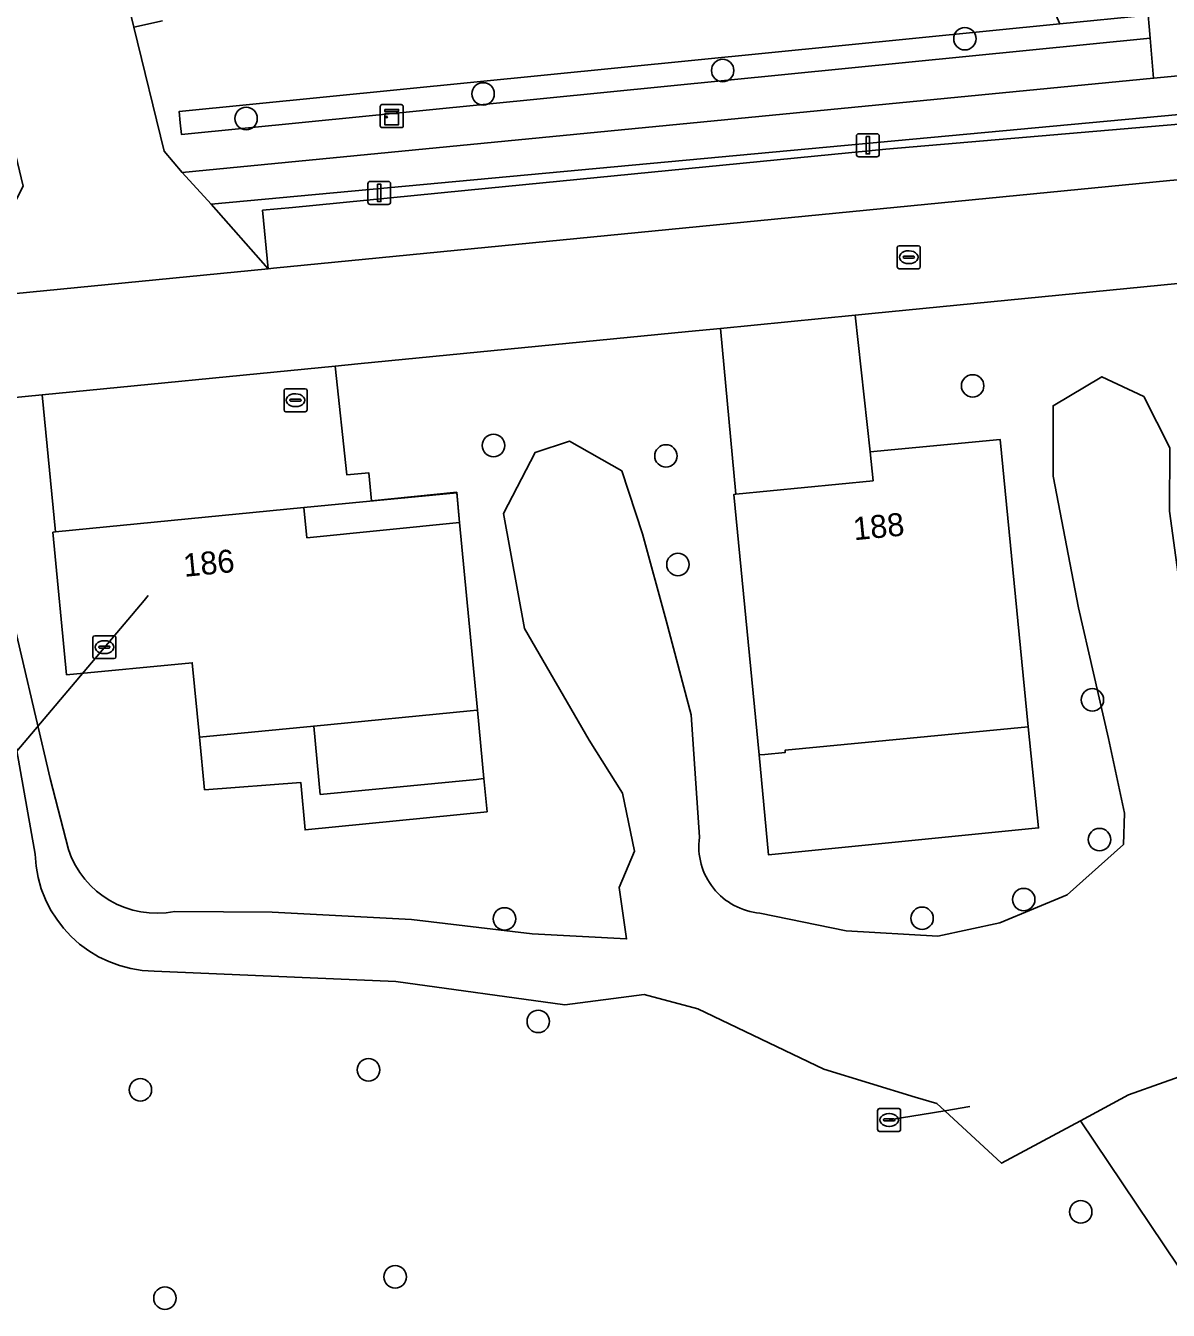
# Model space of a CAD drawing. Extents: x 156661 to 157576, y 383570 to 384425.
# Drawn here: x 156959.7 to 157009.5, y 383880.2 to 383936.2 of the extents above; entities that cross this region are included whole.
import ezdxf

# ---------------------------------------------------------------- set-up
doc = ezdxf.new("R2010")
doc.units = 0
for name, color, linetype in [('IMGEO_Berm_groen', 7, 'Continuous'), ('IMGEO_Boom', 7, 'Continuous'), ('IMGEO_Brandkraan', 7, 'Continuous'), ('IMGEO_Duiker', 7, 'Continuous'), ('IMGEO_Erf', 7, 'Continuous'), ('IMGEO_Groenvoorziening', 7, 'Continuous'), ('IMGEO_Haag', 7, 'Continuous'), ('IMGEO_Kast', 7, 'Continuous'), ('IMGEO_Lichtmast', 7, 'Continuous'), ('IMGEO_Meer_plas_ven_vijver', 7, 'Continuous'), ('IMGEO_Pand', 7, 'Continuous'), ('IMGEO_Pand_nummerreeks', 7, 'Continuous'), ('IMGEO_Pand_overbouw', 7, 'Continuous'), ('IMGEO_Parkeervlak_open', 7, 'Continuous'), ('IMGEO_Rijbaan_lokaal_open', 7, 'Continuous'), ('IMGEO_Rioolput', 7, 'Continuous'), ('IMGEO_Voetpad_open', 7, 'Continuous')]:
    doc.layers.add(name, color=color, linetype=linetype)

msp = doc.modelspace()

# ---------------------------------------------------------------- linework, layer by layer
at = {"layer": 'IMGEO_Berm_groen'}
msp.add_lwpolyline([(157071.526, 383937.018), (157071.115, 383937.537), (157053.882, 383936.219), (157047.285, 383935.737), (157032.066, 383934.37), (156967.792, 383928.413), (156970.285, 383925.601), (156970.036, 383928.144), (156971.344, 383928.273), (156979.881, 383929.112), (156997.191, 383930.813), (157022.212, 383932.944), (157037.851, 383934.234), (157045.273, 383934.895), (157055.512, 383935.702), (157055.71, 383933.229), (157057.249, 383933.355), (157057.154, 383934.404), (157058.945, 383934.553), (157058.941, 383934.597), (157071.071, 383935.569)], dxfattribs=at)
at = {"layer": 'IMGEO_Boom'}
for centre in [(157000.632, 383935.62), (156990.079, 383934.237), (156979.643, 383933.214), (156969.318, 383932.144), (157000.969, 383920.497), (156980.097, 383917.899), (156987.609, 383917.445), (156988.131, 383912.717), (157006.183, 383906.821), (157006.493, 383900.734), (157003.192, 383898.123), (156980.577, 383897.281), (156998.764, 383897.307), (156982.046, 383892.817), (156974.65, 383890.706), (156964.713, 383889.834), (157005.677, 383884.524), (156975.812, 383881.692), (156965.784, 383880.761)]:
    msp.add_circle(centre, 0.489, dxfattribs=at)
at = {"layer": 'IMGEO_Brandkraan'}
for p, q in [((156970.971, 383919.448), (156970.971, 383920.3)), ((156971.046, 383920.374), (156971.898, 383920.374)), ((156971.972, 383920.3), (156971.972, 383919.448)), ((156971.23, 383919.868), (156971.23, 383919.88)), ((156971.668, 383919.831), (156971.27, 383919.831)), ((156971.273, 383919.917), (156971.671, 383919.917)), ((156971.459, 383920.154), (156971.484, 383920.154)), ((156971.714, 383919.88), (156971.714, 383919.868)), ((156971.898, 383919.374), (156971.046, 383919.374)), ((156971.482, 383919.594), (156971.457, 383919.594))]:
    msp.add_line(p, q, dxfattribs=at)
for points in [[(156970.971, 383919.448), (156970.971, 383920.3)], [(156971.046, 383920.374), (156971.898, 383920.374)], [(156971.972, 383920.3), (156971.972, 383919.448)], [(156971.898, 383919.374), (156971.046, 383919.374)]]:
    msp.add_lwpolyline(points, dxfattribs=at)
for centre, radius, start, end in [((156971.048, 383920.298), 0.0765, 91.552, 178.448), ((156971.048, 383920.298), 0.0765, 91.552, 178.448), ((156971.896, 383920.298), 0.0765, 1.552, 88.448), ((156971.896, 383920.298), 0.0765, 1.552, 88.448), ((156971.27, 383919.877), 0.0403, 85.8775, 175.7526), ((156971.267, 383919.867), 0.0366, 178.938, 274.7102), ((156971.671, 383919.874), 0.043, 264.8664, 352.4533), ((156971.675, 383919.879), 0.0386, 1.7309, 96.639), ((156971.048, 383919.45), 0.0765, 181.552, 268.448), ((156971.048, 383919.45), 0.0765, 181.552, 268.448), ((156971.896, 383919.45), 0.0765, 271.552, 358.448), ((156971.896, 383919.45), 0.0765, 271.552, 358.448)]:
    msp.add_arc(centre, radius, start, end, dxfattribs=at)
for centre, major_axis, ratio, start_param, end_param in [((156971.458, 383919.874), (-0.387, 0.002), 0.722429, 4.712389, 7.853982), ((156971.483, 383919.874), (-0.39, 0.002), 0.717154, 1.570796, 4.712389)]:
    msp.add_ellipse(centre, major_axis=major_axis, ratio=ratio, start_param=start_param, end_param=end_param, dxfattribs=at)
at = {"layer": 'IMGEO_Duiker'}
for points in [[(156965.051, 383911.364), (156964.873, 383911.153), (156956.467, 383901.225), (156955.878, 383900.53)], [(157000.842, 383889.109), (156999.755, 383888.928), (156997.332, 383888.523)]]:
    msp.add_lwpolyline(points, dxfattribs=at)
at = {"layer": 'IMGEO_Erf'}
for points in [[(156995.853, 383923.576), (156989.991, 383923.001), (156990.652, 383915.775), (156996.635, 383916.363), (156996.502, 383917.63)], [(156973.202, 383921.355), (156960.429, 383920.102), (156961.014, 383914.134), (156971.834, 383915.203), (156971.965, 383913.88), (156978.62, 383914.545), (156978.494, 383915.861), (156974.785, 383915.495), (156974.663, 383916.711), (156973.714, 383916.616)], [(156979.403, 383906.377), (156979.379, 383906.375), (156979.075, 383906.345), (156972.265, 383905.678), (156967.284, 383905.192), (156967.509, 383902.905), (156971.708, 383903.217), (156971.891, 383901.154), (156979.814, 383901.951), (156979.681, 383903.392)], [(157003.391, 383905.643), (156992.795, 383904.629), (156992.805, 383904.534), (156991.921, 383904.448), (156991.674, 383904.424), (156992.08, 383900.065), (157003.838, 383901.242)]]:
    msp.add_lwpolyline(points, close=True, dxfattribs=at)
at = {"layer": 'IMGEO_Groenvoorziening'}
for points in [[(156953.099, 383937.896), (156882.007, 383929.988), (156863.465, 384006.689), (156971.911, 384032.865), (156984.848, 383993.384), (157001.305, 383943.16), (156963.71, 383939.037), (156964.423, 383936.119), (156965.671, 383936.392)], [(157002.87, 383940.558), (157004.772, 383936.263), (157008.609, 383936.644), (157008.658, 383936.146), (157008.707, 383935.648), (157008.85, 383933.899), (157012.523, 383934.255), (157027.632, 383935.51), (157049.754, 383937.359)], [(156965.671, 383936.392), (156964.423, 383936.119), (156965.744, 383930.718), (156966.535, 383929.792), (157008.85, 383933.899), (157008.707, 383935.648), (156966.501, 383931.453), (156966.452, 383931.95), (156966.402, 383932.448), (157004.772, 383936.263)], [(157009.913, 383924.955), (156996.578, 383923.647), (156995.853, 383923.576), (156996.502, 383917.63), (157002.161, 383918.165), (157003.391, 383905.643), (157003.838, 383901.242), (156992.08, 383900.065), (156991.674, 383904.424), (156990.563, 383915.766), (156990.652, 383915.775), (156989.991, 383923.001), (156988.593, 383922.864), (156974.187, 383921.452), (156973.202, 383921.355), (156973.714, 383916.616), (156974.663, 383916.711), (156974.785, 383915.495), (156978.494, 383915.861), (156978.62, 383914.545), (156979.403, 383906.377), (156979.681, 383903.392), (156979.814, 383901.951), (156971.891, 383901.154), (156971.708, 383903.217), (156967.509, 383902.905), (156967.284, 383905.192), (156966.971, 383908.439), (156961.498, 383907.912), (156960.9, 383914.123), (156961.014, 383914.134), (156960.429, 383920.102), (156912.352, 383915.387)], [(156991.704, 383897.533), (156995.46, 383896.76), (156999.448, 383896.532), (157002.147, 383897.105), (157005.086, 383898.333), (157007.547, 383900.528), (157007.587, 383901.882), (157006.883, 383905.138), (157005.579, 383910.832), (157004.482, 383916.564), (157004.469, 383919.634), (157006.599, 383920.898), (157008.421, 383920.042), (157009.558, 383917.804), (157009.548, 383915.038), (157010.137, 383910.688), (157011.147, 383905.321), (157012.775, 383900.932)], [(156966.214, 383897.609), (156970.461, 383897.569), (156976.53, 383897.255), (156981.775, 383896.629), (156985.893, 383896.412), (156985.576, 383898.642), (156986.234, 383900.228), (156985.71, 383902.762), (156984.257, 383905.07), (156981.444, 383909.929), (156980.534, 383914.932), (156981.914, 383917.602), (156983.408, 383918.095), (156985.69, 383916.795), (156986.591, 383914.049), (156987.619, 383910.28), (156988.702, 383906.17), (156989.065, 383900.834)], [(156960.124, 383900.103), (156957.522, 383914.747), (156958.361, 383914.954), (156958.91, 383911.412), (156960.786, 383903.39), (156961.584, 383900.301)], [(157016.422, 383876.906), (157011.144, 383880.337), (157005.669, 383888.491), (157002.231, 383886.636), (156999.755, 383888.928), (156999.413, 383889.244), (156998.463, 383889.523), (156994.479, 383890.731), (156988.991, 383893.36), (156986.656, 383893.993), (156983.208, 383893.538), (156975.842, 383894.559), (156965.319, 383894.998)]]:
    msp.add_lwpolyline(points, dxfattribs=at)
for points in [[(157008.707, 383935.648), (157008.658, 383936.146), (157008.609, 383936.644), (157004.772, 383936.263), (156966.402, 383932.448), (156966.452, 383931.95), (156966.501, 383931.453)], [(157058.511, 383896.433), (157058.506, 383896.82), (157058.418, 383896.745), (157055.904, 383896.289), (157051.303, 383896.382), (157048.983, 383894.367), (157045.629, 383892.859), (157041.142, 383892.89), (157033.089, 383893.802), (157029.876, 383893.975), (157025.097, 383892.911), (157015.681, 383891.686), (157010.865, 383890.715), (157007.751, 383889.615), (157005.669, 383888.491), (157011.144, 383880.337), (157016.422, 383876.906), (157031.991, 383867.671), (157048.615, 383859.226), (157052.837, 383866.747), (157055.608, 383875.059), (157057.323, 383883.635)]]:
    msp.add_lwpolyline(points, close=True, dxfattribs=at)
for centre, radius, start, end in [((156991.957, 383900.441), 2.919, 172.2587, 265.0228), ((156965.417, 383901.565), 4.036, 198.2547, 281.3957), ((156965.407, 383900.283), 5.286, 181.9547, 269.0466)]:
    msp.add_arc(centre, radius, start, end, dxfattribs=at)
at = {"layer": 'IMGEO_Haag'}
msp.add_lwpolyline([(157008.707, 383935.648), (157008.658, 383936.146), (157008.609, 383936.644), (157004.772, 383936.263), (156966.402, 383932.448), (156966.452, 383931.95), (156966.501, 383931.453)], close=True, dxfattribs=at)
at = {"layer": 'IMGEO_Kast'}
for p, q in [((156975.163, 383931.822), (156975.163, 383932.663)), ((156975.163, 383932.663), (156975.163, 383931.822)), ((156975.238, 383932.747), (156976.079, 383932.747)), ((156976.079, 383932.747), (156975.238, 383932.747)), ((156976.163, 383932.672), (156976.163, 383931.831)), ((156976.163, 383931.831), (156976.163, 383932.672)), ((156976.088, 383931.747), (156975.247, 383931.747)), ((156975.247, 383931.747), (156976.088, 383931.747))]:
    msp.add_line(p, q, dxfattribs=at)
for points in [[(156975.358, 383932.537), (156975.958, 383932.537), (156975.958, 383932.452), (156975.358, 383932.452), (156975.358, 383932.537)], [(156975.358, 383932.362), (156975.958, 383932.362), (156975.958, 383931.873), (156975.358, 383931.873), (156975.358, 383932.362)]]:
    msp.add_lwpolyline(points, dxfattribs=at)
msp.add_circle((156975.442, 383932.211), 0.0377, dxfattribs=at)
for centre, start, end in [((156975.241, 383932.669), 92.4484, 184.2845), ((156975.241, 383932.669), 92.4484, 184.2845), ((156976.085, 383932.669), 2.4484, 94.2845), ((156976.085, 383932.669), 2.4484, 94.2845), ((156975.241, 383931.825), 182.4484, 274.2845), ((156975.241, 383931.825), 182.4484, 274.2845), ((156976.085, 383931.825), 272.4484, 4.2845), ((156976.085, 383931.825), 272.4484, 4.2845)]:
    msp.add_arc(centre, 0.0779, start, end, dxfattribs=at)
at = {"layer": 'IMGEO_Lichtmast'}
for p, q in [((156995.908, 383930.579), (156995.908, 383931.379)), ((156995.908, 383931.379), (156995.908, 383930.579)), ((156996.008, 383931.479), (156996.798, 383931.479)), ((156996.798, 383931.479), (156996.008, 383931.479)), ((156996.898, 383931.379), (156996.898, 383930.579)), ((156996.898, 383930.579), (156996.898, 383931.379)), ((156996.798, 383930.479), (156996.008, 383930.479)), ((156996.008, 383930.479), (156996.798, 383930.479)), ((156974.624, 383928.503), (156974.624, 383929.303)), ((156974.624, 383929.303), (156974.624, 383928.503)), ((156974.724, 383929.403), (156975.514, 383929.403)), ((156975.514, 383929.403), (156974.724, 383929.403)), ((156975.614, 383929.303), (156975.614, 383928.503)), ((156975.614, 383928.503), (156975.614, 383929.303)), ((156975.514, 383928.403), (156974.724, 383928.403)), ((156974.724, 383928.403), (156975.514, 383928.403))]:
    msp.add_line(p, q, dxfattribs=at)
for points in [[(156996.328, 383931.354), (156996.478, 383931.354), (156996.478, 383930.604), (156996.328, 383930.604), (156996.328, 383931.354)], [(156975.044, 383929.278), (156975.194, 383929.278), (156975.194, 383928.528), (156975.044, 383928.528), (156975.044, 383929.278)]]:
    msp.add_lwpolyline(points, dxfattribs=at)
for centre, start, end in [((156996.008, 383931.379), 90, 180), ((156996.008, 383931.379), 90, 180), ((156996.798, 383931.379), 0, 90), ((156996.798, 383931.379), 360, 90), ((156996.008, 383930.579), 180, 270), ((156996.008, 383930.579), 180, 270), ((156996.798, 383930.579), 270, 0), ((156996.798, 383930.579), 270, 0), ((156974.724, 383929.303), 90, 180), ((156974.724, 383929.303), 90, 180), ((156975.514, 383929.303), 0, 90), ((156975.514, 383929.303), 360, 90), ((156974.724, 383928.503), 180, 270), ((156974.724, 383928.503), 180, 270), ((156975.514, 383928.503), 270, 0), ((156975.514, 383928.503), 270, 0)]:
    msp.add_arc(centre, 0.1, start, end, dxfattribs=at)
at = {"layer": 'IMGEO_Meer_plas_ven_vijver'}
for points in [[(157012.775, 383900.932), (157011.147, 383905.321), (157010.137, 383910.688), (157009.548, 383915.038), (157009.558, 383917.804), (157008.421, 383920.042), (157006.599, 383920.898), (157004.469, 383919.634), (157004.482, 383916.564), (157005.579, 383910.832), (157006.883, 383905.138), (157007.587, 383901.882), (157007.547, 383900.528), (157005.086, 383898.333), (157002.147, 383897.105), (156999.448, 383896.532), (156995.46, 383896.76), (156991.704, 383897.533)], [(156989.065, 383900.834), (156988.702, 383906.17), (156987.619, 383910.28), (156986.591, 383914.049), (156985.69, 383916.795), (156983.408, 383918.095), (156981.914, 383917.602), (156980.534, 383914.932), (156981.444, 383909.929), (156984.257, 383905.07), (156985.71, 383902.762), (156986.234, 383900.228), (156985.576, 383898.642), (156985.893, 383896.412), (156981.775, 383896.629), (156976.53, 383897.255), (156970.461, 383897.569), (156966.214, 383897.609)], [(156961.584, 383900.301), (156960.786, 383903.39), (156958.91, 383911.412), (156958.361, 383914.954), (156957.522, 383914.747), (156960.124, 383900.103)], [(156965.319, 383894.998), (156975.842, 383894.559), (156983.208, 383893.538), (156986.656, 383893.993), (156988.991, 383893.36), (156994.479, 383890.731), (156998.463, 383889.523), (156999.413, 383889.244), (156999.755, 383888.928), (157002.231, 383886.636), (157005.669, 383888.491), (157007.751, 383889.615), (157010.865, 383890.715), (157015.681, 383891.686), (157025.097, 383892.911), (157029.876, 383893.975), (157033.089, 383893.802), (157041.142, 383892.89), (157045.629, 383892.859), (157048.983, 383894.367), (157051.303, 383896.382), (157055.904, 383896.289), (157058.418, 383896.745), (157058.506, 383896.82)]]:
    msp.add_lwpolyline(points, dxfattribs=at)
for centre, radius, start, end in [((156991.957, 383900.441), 2.919, 172.2587, 265.0228), ((156965.417, 383901.565), 4.036, 198.2547, 281.3957), ((156965.407, 383900.283), 5.286, 181.9547, 269.0466)]:
    msp.add_arc(centre, radius, start, end, dxfattribs=at)
at = {"layer": 'IMGEO_Pand'}
for points in [[(157002.161, 383918.165), (156996.502, 383917.63), (156996.635, 383916.363), (156990.652, 383915.775), (156990.563, 383915.766), (156991.674, 383904.424), (156991.921, 383904.448), (156992.805, 383904.534), (156992.795, 383904.629), (157003.391, 383905.643)], [(156978.62, 383914.545), (156971.965, 383913.88), (156971.834, 383915.203), (156961.014, 383914.134), (156960.9, 383914.123), (156961.498, 383907.912), (156966.971, 383908.439), (156967.284, 383905.192), (156972.265, 383905.678), (156979.075, 383906.345), (156979.379, 383906.375), (156979.403, 383906.377)]]:
    msp.add_lwpolyline(points, close=True, dxfattribs=at)
at = {"layer": 'IMGEO_Pand_overbouw'}
for points in [[(156978.495, 383915.842), (156971.834, 383915.203), (156971.965, 383913.88), (156978.62, 383914.545)], [(156979.403, 383906.377), (156979.379, 383906.375), (156979.075, 383906.345), (156972.265, 383905.678), (156972.55, 383902.7), (156979.352, 383903.36), (156979.656, 383903.39), (156979.681, 383903.392)]]:
    msp.add_lwpolyline(points, close=True, dxfattribs=at)
at = {"layer": 'IMGEO_Parkeervlak_open'}
msp.add_lwpolyline([(157055.71, 383933.229), (157055.512, 383935.702), (157045.273, 383934.895), (157037.851, 383934.234), (157022.212, 383932.944), (156997.191, 383930.813), (156979.881, 383929.112), (156971.344, 383928.273), (156970.036, 383928.144), (156970.285, 383925.601), (156970.506, 383925.623), (157009.562, 383929.446)], close=True, dxfattribs=at)
at = {"layer": 'IMGEO_Rijbaan_lokaal_open'}
msp.add_lwpolyline([(156963.71, 383939.037), (156963.662, 383939.235), (156962.748, 383943.053), (156961.579, 383942.807), (156961.704, 383942.271), (156961.383, 383942.196), (156961.258, 383942.72), (156959.573, 383949.776), (156954.882, 383948.869), (156956.564, 383941.597), (156956.615, 383941.611), (156956.745, 383941.083), (156957.783, 383936.781), (156959.604, 383929.198), (156958.753, 383927.533), (156957.067, 383924.307), (156970.285, 383925.601), (156967.792, 383928.413), (156966.535, 383929.792), (156965.744, 383930.718), (156964.423, 383936.119)], close=True, dxfattribs=at)
for points in [[(157055.71, 383933.229), (157009.562, 383929.446), (156970.506, 383925.623), (156970.285, 383925.601), (156957.067, 383924.307)], [(156912.352, 383915.387), (156960.429, 383920.102), (156973.202, 383921.355), (156974.187, 383921.452), (156988.593, 383922.864), (156989.991, 383923.001), (156995.853, 383923.576), (156996.578, 383923.647), (157009.913, 383924.955), (157018.161, 383925.629), (157025.823, 383926.256), (157051.661, 383928.368)]]:
    msp.add_lwpolyline(points, dxfattribs=at)
at = {"layer": 'IMGEO_Rioolput'}
for p, q in [((156997.687, 383925.677), (156997.687, 383926.529)), ((156997.762, 383926.603), (156998.614, 383926.603)), ((156998.688, 383926.529), (156998.688, 383925.677)), ((156997.946, 383926.097), (156997.946, 383926.109)), ((156998.384, 383926.06), (156997.986, 383926.06)), ((156997.989, 383926.146), (156998.387, 383926.146)), ((156998.175, 383926.383), (156998.2, 383926.383)), ((156998.43, 383926.109), (156998.43, 383926.097)), ((156998.614, 383925.603), (156997.762, 383925.603)), ((156998.198, 383925.823), (156998.173, 383925.823)), ((156962.648, 383908.691), (156962.648, 383909.543)), ((156962.723, 383909.617), (156963.575, 383909.617)), ((156962.907, 383909.111), (156962.907, 383909.123)), ((156962.95, 383909.16), (156963.348, 383909.16)), ((156963.136, 383909.397), (156963.161, 383909.397)), ((156963.391, 383909.123), (156963.391, 383909.111)), ((156963.649, 383909.543), (156963.649, 383908.691)), ((156963.575, 383908.617), (156962.723, 383908.617)), ((156963.345, 383909.074), (156962.947, 383909.074)), ((156963.159, 383908.837), (156963.134, 383908.837)), ((156996.906, 383889.023), (156997.758, 383889.023)), ((156996.831, 383888.097), (156996.831, 383888.949)), ((156997.09, 383888.517), (156997.09, 383888.529)), ((156997.528, 383888.48), (156997.13, 383888.48)), ((156997.133, 383888.566), (156997.531, 383888.566)), ((156997.319, 383888.803), (156997.344, 383888.803)), ((156997.574, 383888.529), (156997.574, 383888.517)), ((156997.832, 383888.949), (156997.832, 383888.097)), ((156997.758, 383888.023), (156996.906, 383888.023)), ((156997.342, 383888.243), (156997.317, 383888.243))]:
    msp.add_line(p, q, dxfattribs=at)
for points in [[(156997.687, 383925.677), (156997.687, 383926.529)], [(156997.762, 383926.603), (156998.614, 383926.603)], [(156998.688, 383926.529), (156998.688, 383925.677)], [(156998.614, 383925.603), (156997.762, 383925.603)], [(156962.648, 383908.691), (156962.648, 383909.543)], [(156962.723, 383909.617), (156963.575, 383909.617)], [(156963.649, 383909.543), (156963.649, 383908.691)], [(156963.575, 383908.617), (156962.723, 383908.617)], [(156996.906, 383889.023), (156997.758, 383889.023)], [(156996.831, 383888.097), (156996.831, 383888.949)], [(156997.832, 383888.949), (156997.832, 383888.097)], [(156997.758, 383888.023), (156996.906, 383888.023)]]:
    msp.add_lwpolyline(points, dxfattribs=at)
for centre, radius, start, end in [((156997.764, 383926.527), 0.0765, 91.552, 178.448), ((156997.764, 383926.527), 0.0765, 91.552, 178.448), ((156998.612, 383926.527), 0.0765, 1.552, 88.448), ((156998.612, 383926.527), 0.0765, 1.552, 88.448), ((156997.986, 383926.106), 0.0403, 85.8775, 175.7526), ((156997.983, 383926.096), 0.0366, 178.938, 274.7102), ((156998.387, 383926.103), 0.043, 264.8664, 352.4533), ((156998.391, 383926.108), 0.0386, 1.7309, 96.639), ((156997.764, 383925.679), 0.0765, 181.552, 268.448), ((156997.764, 383925.679), 0.0765, 181.552, 268.448), ((156998.612, 383925.679), 0.0765, 271.552, 358.448), ((156998.612, 383925.679), 0.0765, 271.552, 358.448), ((156962.725, 383909.541), 0.0765, 91.552, 178.448), ((156962.725, 383909.541), 0.0765, 91.552, 178.448), ((156962.947, 383909.12), 0.0403, 85.8775, 175.7526), ((156962.944, 383909.11), 0.0366, 178.938, 274.7102), ((156963.348, 383909.117), 0.043, 264.8664, 352.4533), ((156963.352, 383909.122), 0.0386, 1.7309, 96.639), ((156963.573, 383909.541), 0.0765, 1.552, 88.448), ((156963.573, 383909.541), 0.0765, 1.552, 88.448), ((156962.725, 383908.693), 0.0765, 181.552, 268.448), ((156962.725, 383908.693), 0.0765, 181.552, 268.448), ((156963.573, 383908.693), 0.0765, 271.552, 358.448), ((156963.573, 383908.693), 0.0765, 271.552, 358.448), ((156996.908, 383888.947), 0.0765, 91.552, 178.448), ((156996.908, 383888.947), 0.0765, 91.552, 178.448), ((156997.756, 383888.947), 0.0765, 1.552, 88.448), ((156997.756, 383888.947), 0.0765, 1.552, 88.448), ((156997.13, 383888.526), 0.0403, 85.8775, 175.7526), ((156997.127, 383888.516), 0.0366, 178.938, 274.7102), ((156997.531, 383888.523), 0.043, 264.8664, 352.4533), ((156997.535, 383888.528), 0.0386, 1.7309, 96.639), ((156996.908, 383888.099), 0.0765, 181.552, 268.448), ((156996.908, 383888.099), 0.0765, 181.552, 268.448), ((156997.756, 383888.099), 0.0765, 271.552, 358.448), ((156997.756, 383888.099), 0.0765, 271.552, 358.448)]:
    msp.add_arc(centre, radius, start, end, dxfattribs=at)
for centre, major_axis, ratio, start_param, end_param in [((156998.174, 383926.103), (-0.387, 0.002), 0.722429, 4.712389, 7.853982), ((156998.199, 383926.103), (-0.39, 0.002), 0.717154, 1.570796, 4.712389), ((156963.135, 383909.117), (-0.387, 0.002), 0.722429, 4.712389, 7.853982), ((156963.16, 383909.117), (-0.39, 0.002), 0.717154, 1.570796, 4.712389), ((156997.318, 383888.523), (-0.387, 0.002), 0.722429, 4.712389, 7.853982), ((156997.343, 383888.523), (-0.39, 0.002), 0.717154, 1.570796, 4.712389)]:
    msp.add_ellipse(centre, major_axis=major_axis, ratio=ratio, start_param=start_param, end_param=end_param, dxfattribs=at)
at = {"layer": 'IMGEO_Voetpad_open'}
msp.add_lwpolyline([(157083.24, 383940.16), (157075.823, 383939.488), (157069.913, 383939.019), (157067.736, 383938.825), (157049.754, 383937.359), (157027.632, 383935.51), (157012.523, 383934.255), (157008.85, 383933.899), (156966.535, 383929.792), (156967.792, 383928.413), (157032.066, 383934.37), (157047.285, 383935.737)], dxfattribs=at)

# ---------------------------------------------------------------- texts
at = {"layer": 'IMGEO_Pand_nummerreeks'}
for s, rotation, p in [('188', 5.615, (156995.81, 383913.77)), ('186', 5.6436, (156966.631, 383912.177))]:
    msp.add_text(s, height=1, rotation=rotation, dxfattribs=at).set_placement(p)

doc.saveas('drawing.dxf')
